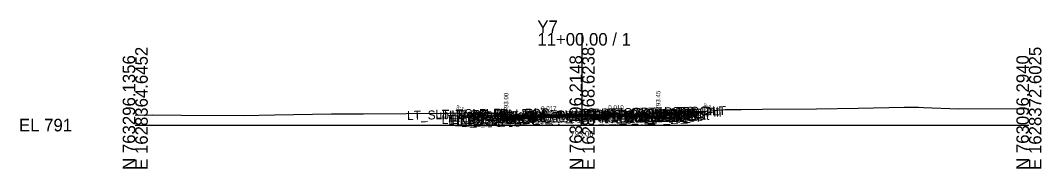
# Model space of a CAD drawing. Extents: x -26 to 203, y -10 to 3017.
# Drawn here: x -25.7 to 202.8, y 1990.3 to 2023.4 of the extents above; entities that cross this region are included whole.
import ezdxf

# ---------------------------------------------------------------- set-up
doc = ezdxf.new("R2010")
doc.units = 0
for name, color, linetype in [('Default', 7, 'Continuous'), ('Exist CMT Pavement', 7, 'Continuous'), ('Exist Cross Section Cell', 7, 'Continuous'), ('Exist XS Center Line Elevation Label', 7, 'Continuous'), ('Exist XS Ground Line', 7, 'Continuous'), ('Prop CMT Conc Surface', 7, 'Continuous'), ('Prop CMT Concrete Structures', 7, 'Continuous'), ('Prop CMT Pvmt Course 1', 7, 'Continuous'), ('Prop CMT Pvmt Course 1 CG', 7, 'Continuous'), ('Prop CMT Pvmt Course 1 Wedge', 7, 'Continuous'), ('Prop CMT Pvmt Course 2', 7, 'Continuous'), ('Prop CMT Pvmt Course 2 Wedge', 7, 'Continuous'), ('Prop CMT Pvmt Course 3', 7, 'Continuous'), ('Prop CMT Pvmt Course 3 Wedge', 7, 'Continuous'), ('Prop CMT Pvmt Surface', 7, 'Continuous'), ('Prop CMT Pvmt Wedge Surface 1', 7, 'Continuous'), ('Prop CMT Pvmt Wedge Surface 2', 7, 'Continuous'), ('Prop CMT Pvmt Wedge Surface 3', 7, 'Continuous'), ('Prop CMT Slope Grass', 7, 'Continuous'), ('Prop CMT Subgrade Earthwork', 7, 'Continuous'), ('Prop XS Hydro Elevations', 7, 'Continuous'), ('Prop XS SE Text', 7, 'Continuous'), ('Prop XS Side Slope Text', 7, 'Continuous'), ('Scratch_Level_0', 7, 'Continuous')]:
    doc.layers.add(name, color=color, linetype=linetype)

msp = doc.modelspace()

# ---------------------------------------------------------------- linework, layer by layer
at = {"layer": 'Exist CMT Pavement'}
for points in [[(100, 2002.06), (99.63, 2002.05), (99.57, 2002.05), (85.07, 2001.41)], [(100, 2002.06), (100.02, 2002.06), (100.11, 2002.05), (100.11, 2002.05), (114.96, 2001.75)]]:
    msp.add_lwpolyline(points, dxfattribs=at)
at = {"layer": 'Exist Cross Section Cell'}
for p, q in [((100, 2000), (100, 2020.55)), ((0, 2000), (100, 2000)), ((100, 2000), (200, 2000))]:
    msp.add_line(p, q, dxfattribs=at)
at = {"layer": 'Exist XS Ground Line'}
msp.add_lwpolyline([(0, 2002.25), (3.84, 2002.29), (10.39, 2002.24), (24.23, 2002.16), (31.18, 2002.27), (43.94, 2002.5), (51.1, 2002.5), (70.24, 2002.66), (74.13, 2002.71), (75.8, 2002.58), (84.67, 2001.58), (85.07, 2001.41), (99.63, 2002.05), (100.11, 2002.05), (114.96, 2001.75), (115.34, 2002.04), (115.9, 2002.09), (132.03, 2003.46), (135.62, 2003.49), (140.39, 2003.53), (152.5, 2003.6), (161.83, 2003.75), (172.09, 2003.98), (175.3, 2004.03), (176.42, 2003.96), (184.23, 2003.64), (197.39, 2003.67), (200, 2003.65)], dxfattribs=at)
at = {"layer": 'Prop CMT Conc Surface'}
for points in [[(83, 2002), (83, 2002.5), (82.5, 2002.5)], [(85, 2002.11), (83, 2002)], [(115.03, 2002.51), (117.03, 2002.45)], [(117.03, 2002.45), (117.03, 2002.95), (117.53, 2002.95)]]:
    msp.add_lwpolyline(points, dxfattribs=at)
at = {"layer": 'Prop CMT Concrete Structures'}
for points in [[(85, 2002.11), (83, 2002), (83, 2002.5), (82.5, 2002.5)], [(82.5, 2002.5), (82.5, 2001.48), (85, 2001.53)], [(85, 2001.53), (85, 2002.11)], [(115.03, 2002.51), (117.03, 2002.45), (117.03, 2002.95), (117.53, 2002.95)], [(117.53, 2002.95), (117.53, 2001.95), (115.03, 2001.93)], [(115.03, 2001.93), (115.03, 2002.51)]]:
    msp.add_lwpolyline(points, dxfattribs=at)
at = {"layer": 'Prop CMT Pvmt Course 1'}
for points in [[(100, 2002.36), (85, 2002.11)], [(85, 2002.11), (85, 2001.86)], [(85.07, 2001.99), (100, 2002.23)], [(85.07, 2001.86), (85.07, 2001.99)], [(100, 2002.36), (115.03, 2002.51)], [(114.96, 2002.38), (100, 2002.23)], [(100, 2002.11), (100, 2002.36)], [(100, 2002.11), (100, 2002.36)], [(100, 2002.23), (100, 2002.11), (100, 2002.11)], [(100, 2002.23), (100, 2002.11), (100, 2002.11)], [(114.96, 2002.26), (114.96, 2002.38)], [(115.03, 2002.26), (114.96, 2002.26)], [(115.03, 2002.51), (115.03, 2002.26)], [(85, 2001.86), (85.07, 2001.86)]]:
    msp.add_lwpolyline(points, dxfattribs=at)
at = {"layer": 'Prop CMT Pvmt Course 1 CG'}
for points in [[(115.03, 2001.93), (118.03, 2001.96), (118.36, 2001.63)], [(85, 2001.53), (82, 2001.48), (81.66, 2001.14)], [(81.66, 2001.14), (85, 2001.19)], [(85, 2001.19), (85, 2001.53)], [(115.03, 2001.59), (115.03, 2001.93)], [(118.36, 2001.63), (115.03, 2001.59)]]:
    msp.add_lwpolyline(points, dxfattribs=at)
at = {"layer": 'Prop CMT Pvmt Course 1 Wedge'}
for points in [[(85.07, 2001.99), (99.57, 2002.23), (99.63, 2002.23), (100, 2002.23)], [(100, 2002.11), (99.63, 2002.1), (99.57, 2002.1), (85.07, 2001.86)], [(85.07, 2001.99), (85.07, 2001.99)], [(85.07, 2001.86), (85.07, 2001.99)], [(100, 2002.23), (100.02, 2002.23), (100.11, 2002.24), (100.11, 2002.24), (114.96, 2002.38)], [(114.96, 2002.26), (100.11, 2002.11), (100.11, 2002.11), (100.02, 2002.11), (100, 2002.11)], [(100, 2002.23), (100, 2002.11)], [(100, 2002.11), (100, 2002.23)], [(114.96, 2002.38), (114.96, 2002.26), (114.96, 2002.26)], [(85.07, 2001.86), (85.07, 2001.86)]]:
    msp.add_lwpolyline(points, dxfattribs=at)
at = {"layer": 'Prop CMT Pvmt Course 2'}
for points in [[(114.96, 2001.93), (114.96, 2002.26)], [(114.96, 2002.26), (115.03, 2002.26)], [(115.03, 2002.26), (115.03, 2001.93)], [(85.07, 2001.86), (85, 2001.86)], [(85, 2001.86), (85, 2001.53)], [(85, 2001.53), (85.07, 2001.53)], [(85.07, 2001.53), (85.07, 2001.86)], [(115.03, 2001.93), (114.96, 2001.93)]]:
    msp.add_lwpolyline(points, dxfattribs=at)
at = {"layer": 'Prop CMT Pvmt Course 2 Wedge'}
for points in [[(85.07, 2001.86), (99.57, 2002.1), (99.63, 2002.1), (100, 2002.11)], [(100, 2002.06), (99.63, 2002.05), (99.57, 2002.05), (89.46, 2001.6), (85.07, 2001.53)], [(100, 2002.11), (100.02, 2002.11), (100.11, 2002.11), (100.11, 2002.11), (114.96, 2002.26)], [(100, 2002.11), (100, 2002.06)], [(100, 2002.06), (100, 2002.11)], [(114.96, 2001.93), (109.16, 2001.87), (100.11, 2002.05), (100.11, 2002.05), (100.02, 2002.06), (100, 2002.06)], [(114.96, 2002.26), (114.96, 2001.93), (114.96, 2001.93)], [(85.07, 2001.86), (85.07, 2001.86)], [(85.07, 2001.53), (85.07, 2001.86)], [(85.07, 2001.53), (85.07, 2001.53)]]:
    msp.add_lwpolyline(points, dxfattribs=at)
at = {"layer": 'Prop CMT Pvmt Course 3'}
for points in [[(85.07, 2001.53), (85, 2001.53)], [(85, 2001.53), (85, 2001.19)], [(85, 2001.19), (85.07, 2001.19)], [(85.07, 2001.19), (85.07, 2001.53)], [(114.96, 2001.93), (115.03, 2001.93)], [(114.96, 2001.59), (114.96, 2001.93)], [(115.03, 2001.59), (114.96, 2001.59)], [(115.03, 2001.93), (115.03, 2001.59)]]:
    msp.add_lwpolyline(points, dxfattribs=at)
at = {"layer": 'Prop CMT Pvmt Course 3 Wedge'}
for points in [[(85.07, 2001.53), (89.46, 2001.6)], [(89.46, 2001.6), (85.07, 2001.41)], [(85.07, 2001.53), (85.07, 2001.53)], [(85.07, 2001.41), (85.07, 2001.53)], [(85.07, 2001.41), (85.07, 2001.41)], [(109.16, 2001.87), (114.96, 2001.93)], [(114.96, 2001.75), (109.16, 2001.87)], [(114.96, 2001.93), (114.96, 2001.75), (114.96, 2001.75)]]:
    msp.add_lwpolyline(points, dxfattribs=at)
at = {"layer": 'Prop CMT Pvmt Surface'}
for points in [[(100, 2002.36), (85, 2002.11)], [(100, 2002.36), (115.03, 2002.51)]]:
    msp.add_lwpolyline(points, dxfattribs=at)
at = {"layer": 'Prop CMT Pvmt Wedge Surface 1'}
for points in [[(85, 2001.86), (85, 2002.11)], [(100, 2002.23), (85.07, 2001.99)], [(85.07, 2001.99), (85.07, 2001.86)], [(100, 2002.23), (114.96, 2002.38)], [(114.96, 2002.38), (114.96, 2002.26)], [(114.96, 2002.26), (115.03, 2002.26)], [(115.03, 2002.26), (115.03, 2002.51)], [(85.07, 2001.86), (85, 2001.86)]]:
    msp.add_lwpolyline(points, dxfattribs=at)
at = {"layer": 'Prop CMT Pvmt Wedge Surface 2'}
for points in [[(100, 2002.11), (85, 2001.86)], [(85, 2001.86), (85, 2002.11)], [(100, 2002.11), (115.03, 2002.26)], [(115.03, 2002.26), (115.03, 2002.51)]]:
    msp.add_lwpolyline(points, dxfattribs=at)
at = {"layer": 'Prop CMT Pvmt Wedge Surface 3'}
for points in [[(85, 2001.53), (85, 2002.11)], [(115.03, 2001.93), (115.03, 2002.51)], [(100, 2001.78), (85, 2001.53)], [(100, 2001.78), (115.03, 2001.93)]]:
    msp.add_lwpolyline(points, dxfattribs=at)
at = {"layer": 'Prop CMT Slope Grass'}
for points in [[(72.97, 2002.7), (73, 2002.69)], [(82.5, 2002.5), (73, 2002.69)], [(117.53, 2002.95), (127.03, 2003.14)], [(127.03, 2003.14), (127.28, 2003.06)]]:
    msp.add_lwpolyline(points, dxfattribs=at)
at = {"layer": 'Prop CMT Subgrade Earthwork'}
for points in [[(85, 2001.19), (81.66, 2001.14), (80.26, 2002.54)], [(115.03, 2001.59), (118.36, 2001.63), (119.72, 2002.99)], [(85.07, 2001.19), (85, 2001.19)], [(85.07, 2001.19), (85.09, 2001.41)], [(114.96, 2001.59), (114.94, 2001.75)], [(114.96, 2001.59), (115.03, 2001.59)]]:
    msp.add_lwpolyline(points, dxfattribs=at)

# ---------------------------------------------------------------- texts
at = {"layer": 'Default'}
msp.add_text('-', height=0.0001, dxfattribs=at).set_placement((0, 2000))
at = {"layer": 'Exist Cross Section Cell'}
for s, p in [('Y7', (90, 2020.55)), ('11+00.00 / 1', (90, 2017.75)), ('EL 791', (-26, 1998.6))]:
    msp.add_text(s, height=2.8, dxfattribs=at).set_placement(p)
for s, p in [('E 1628364.6452', (2.8, 1990)), ('E 1628368.6238', (102.8, 1990)), ('E 1628372.6025', (202.8, 1990)), ('N 763296.1356', (0, 1990)), ('N 763196.2148', (100, 1990)), ('N 763096.2940', (200, 1990))]:
    msp.add_text(s, height=2.8, rotation=90, dxfattribs=at).set_placement(p)
at = {"layer": 'Exist XS Center Line Elevation Label'}
msp.add_text('793.06', height=1.2, dxfattribs=at).set_placement((97.45, 1997.46))
at = {"layer": 'Prop XS Hydro Elevations'}
for s, p in [('793.00', (83.5, 2003)), ('793.45', (117.53, 2003.45))]:
    msp.add_text(s, height=1, rotation=90, dxfattribs=at).set_placement(p)
at = {"layer": 'Prop XS SE Text'}
for s, rotation, p in [('0.017', 0.9548, (90.85, 2003.21)), ('0.010', 0.5729, (105.87, 2003.42))]:
    msp.add_text(s, height=1, rotation=rotation, dxfattribs=at).set_placement(p)
at = {"layer": 'Prop XS Side Slope Text'}
for p in [(71.64, 2003.53), (126.95, 2003.96)]:
    msp.add_text('3:1', height=1, rotation=341.5668, dxfattribs=at).set_placement(p)
at = {"layer": 'Scratch_Level_0'}
for s, p in [('RT_Sub_Trench_Out_DLT', (100.27, 2001.6)), ('LT_Sub_Trench_Out_DLT', (60.85, 2001.15)), ('LT_Slope_Fill', (67.18, 2001.3)), ('LT_CSLP_Pnt', (67.19, 2001.41)), ('LT_CG1_Shelf_Out', (68.57, 2000.21)), ('LT_PV_Sub_Tie_Out', (70.05, 2000.11)), ('LT_CG_Top_Face', (70.28, 2001.24)), ('LT_CG_Top_BOC', (70.8, 2001.26)), ('LT_CG_Bot_BOC', (70.84, 2000.25)), ('LT_CG_Top_Gut', (71.26, 2000.76)), ('LT_Sub_OEOP', (71.79, 1999.94)), ('LT_PV_OEEOP_EG', (72.64, 2000.16)), ('LT_Sub_OEEOP', (74.31, 1999.98)), ('LT_PV2_OEEOP', (74.4, 2000.65)), ('LT_PV3_OEEOP', (74.4, 2000.31)), ('LT_CG_Bot_IE', (74.94, 2000.32)), ('LT_PV1_OEEOP', (74.97, 2000.78)), ('LT_Sub_OEOT', (75.1, 1999.99)), ('LT_PV2_OEOT', (75.2, 2000.66)), ('LT_PV3_OEOT', (75.2, 2000.33)), ('LT_PV1_OEOT', (75.76, 2000.92)), ('RT_PV_IEEOP_EG', (88.16, 2000.82)), ('LT_PV_IEEOP_EG', (88.21, 2000.82)), ('RT_PV2_IEEOP', (89.93, 2000.91)), ('RT_PV3_IEEOP', (89.93, 2000.57)), ('LT_PV2_IEEOP', (89.97, 2000.91)), ('LT_PV3_IEEOP', (89.97, 2000.58)), ('RT_PV1_IEEOP', (90.49, 2001.04)), ('LT_PV1_IEEOP', (90.54, 2001.05)), ('PV2_PGL', (93.93, 2000.99)), ('PV1_PGL', (94.49, 2001.25)), ('RT_PV_Sub_Tie_Out', (99.86, 2000.45)), ('RT_PV_OEEOP_EG', (102.48, 2000.5)), ('RT_Sub_OEEOP', (104.15, 2000.38)), ('RT_PV2_OEEOP', (104.24, 2001.04)), ('RT_PV3_OEEOP', (104.24, 2000.71)), ('RT_CG_Top_Face', (104.26, 2001.69)), ('RT_CG1_Shelf_Out', (104.55, 2000.69)), ('RT_PV1_OEEOP', (104.81, 2001.18)), ('RT_CG_Bot_IE', (104.92, 2000.72)), ('RT_Sub_OEOT', (105.08, 2000.39)), ('RT_PV2_OEOT', (105.17, 2001.06)), ('RT_PV3_OEOT', (105.17, 2000.73)), ('RT_CG_Top_Gut', (105.24, 2001.21)), ('RT_PV1_OEOT', (105.74, 2001.32)), ('RT_CG_Top_BOC', (105.79, 2001.71)), ('RT_CG_Bot_BOC', (105.82, 2000.72)), ('RT_Sub_OEOP', (108.44, 2000.43)), ('RT_CSLP_Pnt', (113.18, 2001.86)), ('RT_Slope_Fill', (114.39, 2001.58))]:
    msp.add_text(s, height=2, rotation=1.1458, dxfattribs=at).set_placement(p)

doc.saveas('drawing.dxf')
